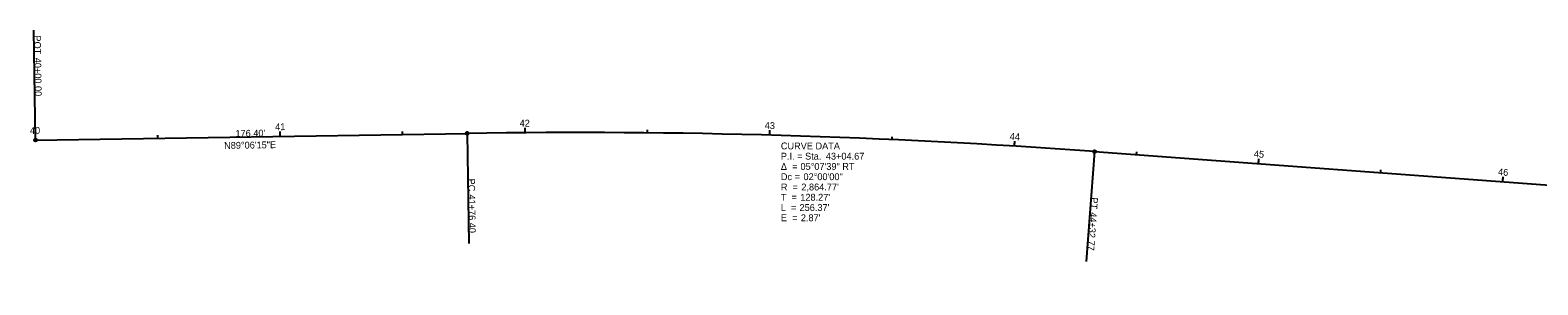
# Model space of a CAD drawing. Extents: x 1459328 to 1461822, y 481336 to 484746.
# Drawn here: x 1459328 to 1459944, y 482512 to 482616 of the extents above; entities that cross this region are included whole.
import ezdxf

# ---------------------------------------------------------------- set-up
doc = ezdxf.new("R2010")
doc.units = 0
for name, color, linetype in [('BR_X_SV_Abut', 7, 'Continuous'), ('PM_X_Cells', 7, 'Continuous'), ('PM_X_Surveyed_Line', 7, 'Continuous'), ('PV_X_COP', 7, 'Continuous'), ('PV_X_Curb', 7, 'Continuous'), ('PV_X_EOP', 7, 'Continuous'), ('PV_X_Shoulder_Aggregate', 7, 'Continuous'), ('RD_X_GR_Bar', 7, 'Continuous'), ('RD_X_GR_Lt', 7, 'Continuous'), ('RD_X_GR_Rt', 7, 'Continuous'), ('RW_X_Esmt_SH', 7, 'Continuous'), ('SN_X_Public', 7, 'Continuous'), ('SV_X_Break_Lines', 7, 'Continuous'), ('SV_X_Random_Point', 7, 'Continuous'), ('SV_X_Toe_of_Slope', 7, 'Continuous'), ('SV_X_Top_of_Bank', 7, 'Continuous')]:
    doc.layers.add(name, color=color, linetype=linetype)

msp = doc.modelspace()

# ---------------------------------------------------------------- linework, layer by layer
at = {"layer": 'BR_X_SV_Abut'}
for p, q in [((1459330.18, 482571.49), (1459329.48, 482616.48)), ((1459506.56, 482574.25), (1459507.26, 482529.25)), ((1459762.74, 482566.79), (1459759.41, 482521.91))]:
    msp.add_line(p, q, dxfattribs=at)
for centre in [(1459506.56, 482574.25), (1459330.18, 482571.49), (1459762.74, 482566.79)]:
    msp.add_circle(centre, 0.6, dxfattribs=at)
at = {"layer": 'PV_X_EOP'}
for p, q in [((1459330.18, 482571.49), (1459330.15, 482573.49)), ((1459380.18, 482572.27), (1459380.16, 482573.47)), ((1459430.17, 482573.05), (1459430.14, 482575.05)), ((1459480.16, 482573.83), (1459480.15, 482575.03)), ((1459530.16, 482574.52), (1459530.15, 482576.52)), ((1459580.16, 482574.45), (1459580.17, 482575.65)), ((1459630.15, 482573.51), (1459630.2, 482575.51)), ((1459680.12, 482571.7), (1459680.17, 482572.9)), ((1459730.04, 482569.02), (1459730.17, 482571.01)), ((1459779.92, 482565.52), (1459780.01, 482566.71)), ((1459829.78, 482561.83), (1459829.93, 482563.82)), ((1459879.65, 482558.14), (1459879.74, 482559.33)), ((1459929.51, 482554.45), (1459929.66, 482556.44))]:
    msp.add_line(p, q, dxfattribs=at)
at = {"layer": 'PV_X_Shoulder_Aggregate'}
for p, q in [((1459330.18, 482571.49), (1459329.48, 482616.48)), ((1459506.56, 482574.25), (1459507.26, 482529.25)), ((1459762.74, 482566.79), (1459759.41, 482521.91))]:
    msp.add_line(p, q, dxfattribs=at)
for centre in [(1459506.56, 482574.25), (1459330.18, 482571.49), (1459762.74, 482566.79)]:
    msp.add_circle(centre, 0.6, dxfattribs=at)
at = {"layer": 'RD_X_GR_Lt'}
for p, q in [((1459330.18, 482571.49), (1459330.15, 482573.49)), ((1459829.78, 482561.83), (1459829.87, 482563.02))]:
    msp.add_line(p, q, dxfattribs=at)
at = {"layer": 'RW_X_Esmt_SH'}
for p, q in [((1459330.18, 482571.49), (1459506.56, 482574.25)), ((1459330.18, 482571.49), (1459506.56, 482574.25)), ((1459762.74, 482566.79), (1460499.29, 482512.29)), ((1459762.74, 482566.79), (1460499.29, 482512.29))]:
    msp.add_line(p, q, dxfattribs=at)
msp.add_arc((1459551.34, 479709.83), 2864.77, 85.76832, 90.89572, dxfattribs=at)
msp.add_arc((1459551.34, 479709.83), 2864.77, 85.76832, 90.89572, dxfattribs=at)
at = {"layer": 'SV_X_Break_Lines'}
for p, q in [((1459330.18, 482571.49), (1459330.15, 482573.49)), ((1459430.17, 482573.05), (1459430.15, 482574.25)), ((1459530.16, 482574.52), (1459530.15, 482575.72)), ((1459630.15, 482573.51), (1459630.18, 482574.71)), ((1459730.04, 482569.02), (1459730.12, 482570.22)), ((1459829.78, 482561.83), (1459829.93, 482563.82)), ((1459929.51, 482554.45), (1459929.6, 482555.64))]:
    msp.add_line(p, q, dxfattribs=at)
at = {"layer": 'SV_X_Top_of_Bank'}
for p, q in [((1459330.18, 482571.49), (1459329.48, 482616.48)), ((1459506.56, 482574.25), (1459507.26, 482529.25)), ((1459762.74, 482566.79), (1459759.41, 482521.91))]:
    msp.add_line(p, q, dxfattribs=at)
for centre in [(1459506.56, 482574.25), (1459330.18, 482571.49), (1459762.74, 482566.79)]:
    msp.add_circle(centre, 0.6, dxfattribs=at)

# ---------------------------------------------------------------- texts
at = {"layer": 'BR_X_SV_Abut'}
for s, rotation, p in [('POT', 270.89572, (1459329.56, 482614.28)), ('40+00.00', 270.89572, (1459329.7, 482605.15)), ('PC', 270.89572, (1459506.9, 482555.74)), ('41+76.40', 270.89572, (1459507, 482549.22)), ('PT', 265.76832, (1459761.4, 482548.16)), ('44+32.77', 265.76832, (1459760.96, 482542.09))]:
    msp.add_text(s, height=2.8, rotation=rotation, dxfattribs=at).set_placement(p)
at = {"layer": 'PM_X_Cells'}
msp.add_text("176.40'", height=2.8, rotation=0.89572, dxfattribs=at).set_placement((1459411.89, 482572.81))
at = {"layer": 'PM_X_Surveyed_Line'}
for s, p in [('CURVE DATA', (1459634.65, 482567.72)), ('Δ  = ', (1459634.65, 482559.32)), ('P.I. = Sta. ', (1459634.65, 482563.52)), ('05°07\'39" RT', (1459642.67, 482559.32)), ('43+04.67', (1459653.02, 482563.52)), ('Dc = ', (1459634.65, 482555.12)), ('02°00\'00"', (1459643.89, 482555.12)), ('T  = ', (1459634.65, 482546.72)), ('R  = ', (1459634.65, 482550.92)), ("128.27'", (1459642.58, 482546.72)), ("2,864.77'", (1459643.02, 482550.92)), ('L  = ', (1459634.65, 482542.52)), ("256.37'", (1459642.29, 482542.52)), ('E  = ', (1459634.65, 482538.32)), ("2.87'", (1459642.8, 482538.32))]:
    msp.add_text(s, height=2.8, dxfattribs=at).set_placement(p)
at = {"layer": 'PV_X_COP'}
msp.add_text('N89°06\'15"E', height=2.8, rotation=0.89572, dxfattribs=at).set_placement((1459407.27, 482567.89))
at = {"layer": 'PV_X_Curb'}
for s, p in [('CURVE DATA', (1459634.65, 482567.72)), ('Δ  = ', (1459634.65, 482559.32)), ('P.I. = Sta. ', (1459634.65, 482563.52)), ('05°07\'39" RT', (1459642.67, 482559.32)), ('43+04.67', (1459653.02, 482563.52)), ('Dc = ', (1459634.65, 482555.12)), ('02°00\'00"', (1459643.89, 482555.12)), ('T  = ', (1459634.65, 482546.72)), ('R  = ', (1459634.65, 482550.92)), ("128.27'", (1459642.58, 482546.72)), ("2,864.77'", (1459643.02, 482550.92)), ('L  = ', (1459634.65, 482542.52)), ("256.37'", (1459642.29, 482542.52)), ('E  = ', (1459634.65, 482538.32)), ("2.87'", (1459642.8, 482538.32))]:
    msp.add_text(s, height=2.8, dxfattribs=at).set_placement(p)
at = {"layer": 'PV_X_EOP'}
for s, rotation, p in [('42', 0.4237, (1459527.96, 482577)), ('40', 0.89572, (1459327.95, 482574)), ('41', 0.89572, (1459428.11, 482575.52)), ('43', 358.42368, (1459628.04, 482576.12)), ('44', 356.42367, (1459728.05, 482571.65)), ('45', 355.76832, (1459827.77, 482564.53)), ('46', 355.76832, (1459927.51, 482557.15))]:
    msp.add_text(s, height=2.8, rotation=rotation, dxfattribs=at).set_placement(p)
at = {"layer": 'PV_X_Shoulder_Aggregate'}
for s, rotation, p in [('POT', 270.89572, (1459329.56, 482614.28)), ('40+00.00', 270.89572, (1459329.7, 482605.15)), ('PC', 270.89572, (1459506.9, 482555.74)), ('41+76.40', 270.89572, (1459507, 482549.22)), ('PT', 265.76832, (1459761.4, 482548.16)), ('44+32.77', 265.76832, (1459760.96, 482542.09))]:
    msp.add_text(s, height=2.8, rotation=rotation, dxfattribs=at).set_placement(p)
at = {"layer": 'RD_X_GR_Bar'}
for s, p in [('CURVE DATA', (1459634.65, 482567.72)), ('Δ  = ', (1459634.65, 482559.32)), ('P.I. = Sta. ', (1459634.65, 482563.52)), ('05°07\'39" RT', (1459642.67, 482559.32)), ('43+04.67', (1459653.02, 482563.52)), ('Dc = ', (1459634.65, 482555.12)), ('02°00\'00"', (1459643.89, 482555.12)), ('T  = ', (1459634.65, 482546.72)), ('R  = ', (1459634.65, 482550.92)), ("128.27'", (1459642.58, 482546.72)), ("2,864.77'", (1459643.02, 482550.92)), ('L  = ', (1459634.65, 482542.52)), ("256.37'", (1459642.29, 482542.52)), ('E  = ', (1459634.65, 482538.32)), ("2.87'", (1459642.8, 482538.32))]:
    msp.add_text(s, height=2.8, dxfattribs=at).set_placement(p)
at = {"layer": 'RD_X_GR_Lt'}
msp.add_text('40', height=2.8, rotation=0.89572, dxfattribs=at).set_placement((1459327.95, 482574))
at = {"layer": 'RD_X_GR_Rt'}
msp.add_text('N89°06\'15"E', height=2.8, rotation=0.89572, dxfattribs=at).set_placement((1459407.27, 482567.89))
at = {"layer": 'SN_X_Public'}
msp.add_text("176.40'", height=2.8, rotation=0.89572, dxfattribs=at).set_placement((1459411.89, 482572.81))
at = {"layer": 'SV_X_Break_Lines'}
for s, rotation, p in [('40', 0.89572, (1459327.95, 482574)), ('45', 355.76832, (1459827.77, 482564.53))]:
    msp.add_text(s, height=2.8, rotation=rotation, dxfattribs=at).set_placement(p)
at = {"layer": 'SV_X_Random_Point'}
msp.add_text("176.40'", height=2.8, rotation=0.89572, dxfattribs=at).set_placement((1459411.89, 482572.81))
at = {"layer": 'SV_X_Toe_of_Slope'}
msp.add_text('N89°06\'15"E', height=2.8, rotation=0.89572, dxfattribs=at).set_placement((1459407.27, 482567.89))
at = {"layer": 'SV_X_Top_of_Bank'}
for s, rotation, p in [('POT', 270.89572, (1459329.56, 482614.28)), ('40+00.00', 270.89572, (1459329.7, 482605.15)), ('PC', 270.89572, (1459506.9, 482555.74)), ('41+76.40', 270.89572, (1459507, 482549.22)), ('PT', 265.76832, (1459761.4, 482548.16)), ('44+32.77', 265.76832, (1459760.96, 482542.09))]:
    msp.add_text(s, height=2.8, rotation=rotation, dxfattribs=at).set_placement(p)

doc.saveas('drawing.dxf')
